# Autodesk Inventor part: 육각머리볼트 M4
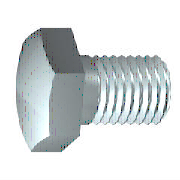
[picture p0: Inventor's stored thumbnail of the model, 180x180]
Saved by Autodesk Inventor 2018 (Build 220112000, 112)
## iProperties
Created: 2012-02
Part Number: 육각머리볼트 M4
Material: 스테인리스강
Description: 6각 머리 나사
Document SubType Name: Modeling
Standard: ISO 4017
Designer: mduedu
Standard Revision: Third edition 1999-08-15
Standards Organization: ISO
Language: ko-KR
Size Designation: M4 x 10
Categories: <MemberInstance><Categories><Category DisplayName="조임쇠" InternalName="e4da775c-781d-43d5-af7c-5136215cf5a6" Mnemonic="FSTN"><Category DisplayName="볼트" InternalN
Density: 8.08 g/cm^3
Appearance: 반광택
IsCustomPart: 0
Author: mduedu
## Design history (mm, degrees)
sketch "스케치1"
  geometry: L1 (0, 3.015)-(0, 2); L2 (1.75, 2)-(10, 2); L3 (10, 2)-(10, 0); L4 (10, 0)-(-0.4, 0); L5 (-2.48, 0)-(12.08, 0) reference; L6 (-0.4, 0)-(-0.4, 3.015); L7 (-0.4, 3.015)-(0, 3.015); L8 (1.75, 2)-(1.32, 2); L9 (1.32, 2)-(0, 2); L10 (0, -0.603)-(0, 3.618) reference
  constraints: 16 end point, 2 collinear, 2 perpendicular, 1 parallel
  dimensions: "d0" = 10 distance between parallel lines of L3 L1 (= NLG); "d1" = 8.25 distance from line of L2.start L3 (= GEL); "d2" = 4 diameter of L2 L4 (= GD); "d9" = 0.4001 distance between parallel lines of L6 L1 (computed from SD); "d10" = 6.03 diameter of L7 L4 (= SD2); "d13" = 0.42952 distance of L2.start L8.end (computed from GAL); "d14" = 4 diameter of L9 L4 (= BDM)
revolve "본체" sketch "스케치1" stored, may be unused: angle "d12" = 90 deg
sketch "스케치2"
  geometry: L1 (0, 4.041)-(3.5, 2.021); L2 (3.5, 2.021)-(3.5, -2.021); L3 (3.5, -2.021)-(0, -4.041); L4 (0, -4.041)-(-3.5, -2.021); L5 (-3.5, -2.021)-(-3.5, 2.021); L6 (-3.5, 2.021)-(0, 4.041); 2 further points
  constraints: 12 end point, 1 coincident, 1 vertical, 11 other
  dimensions: "d11" = 7 distance between parallel lines of L5 L2 (= SW)
extrude "머리" join sketch "스케치2" distance "d3" = 2.4 (= KOH - SD); taper "d4" = 0 deg
sketch "스케치4"
  geometry: L1 (-2.8, 3.5)-(-2.8, 4.041); L2 (-2.8, 4.041)-(-2.487, 4.041); L3 (-2.487, 4.041)-(-2.8, 3.5); L4 (-3.28, 0)-(0.08, 0) reference; L5 (-0.4, 4.041)-(-2.8, 4.041) reference; L6 (-2.8, 2.021)-(-2.8, 4.041) reference
  constraints: 6 end point, 2 collinear, 1 perpendicular, 1 vertical
  dimensions: "d5" = 30 deg angle of L3 L1 (= ANG1); "d19" = 7 diameter of L1.start L4 (= SW0)
revolve "모따기1" sketch "스케치4" stored, may be unused: angle "d21" = 90 deg
workplane "Work Plane1"
body "Solid1"
feature "스레드" dims "d15" = 8.25 (= GEL), "d16" = 0
chamfer "모따기2" distance "d6" = 0.42941 (= -0.5 x SPD + 0.5 x GD); stored, may be unused: second distance "d7" = 0.42952 (computed from GUL), angle "d55" = 45 deg
other parameters: "NLG" = 10 [user parameter; used in 1 equation term], "GD" = 4 (= NND) [user parameter; used in 2 equation terms], "BDM" = 4 (= NND) [user parameter; used in 1 equation term], "KOH" = 2.8 [user parameter; used in 1 equation term], "GEL" = 8.25 [user parameter; used in 2 equation terms], "SW" = 7 [user parameter; used in 2 equation terms], "SW0" = 7 (= SW) [user parameter; used in 1 equation term], "SPD" = 3.14117 (= NND - 1.2269 x PTC) [user parameter; used in 1 equation term], "SD2" = 6.03 [user parameter; used in 2 equation terms], "SD" = 0.4 [user parameter; used in 2 equation terms], "ANG1" = 30 deg [user parameter; used in 1 equation term], "GAL" = 0.42941 (= 0.61345 x PTC) [user parameter; used in 1 equation term], "GUL" = 0.42941 (= 0.61345 x PTC) [user parameter; used in 1 equation term], "d8" = 0, "RR" = 0.2 [user parameter], "d57" = 0, "d58" = 0, "TPU" = 14.28571 (computed from PTC) [user parameter], "GD1" = 3.14117 (= THREADDIA - 1.2269 x PTC) [user parameter], "THREADDIA" = 4 [user parameter; used in 1 equation term], "SDH" = 6.03 (= SD2) [user parameter], "SDHG" = 2.1 [user parameter], "TOA" = 30 deg [user parameter], "PTC" = 0.7 [user parameter; used in 5 equation terms], "NND" = 4 [user parameter; used in 3 equation terms], "E0" = 8.085 [user parameter]
